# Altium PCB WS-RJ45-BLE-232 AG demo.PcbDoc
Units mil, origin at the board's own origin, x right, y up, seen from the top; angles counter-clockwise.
Board outline 2362.2 x 1181.1 mil, 3 copper layers (Top Layer, Mid-Layer 1, Bottom Layer), stack 74.411 mil thick; 17 components, 28 nets, 68 pads, 0 vias.
Unrouted connection lines stored in the file: 9.
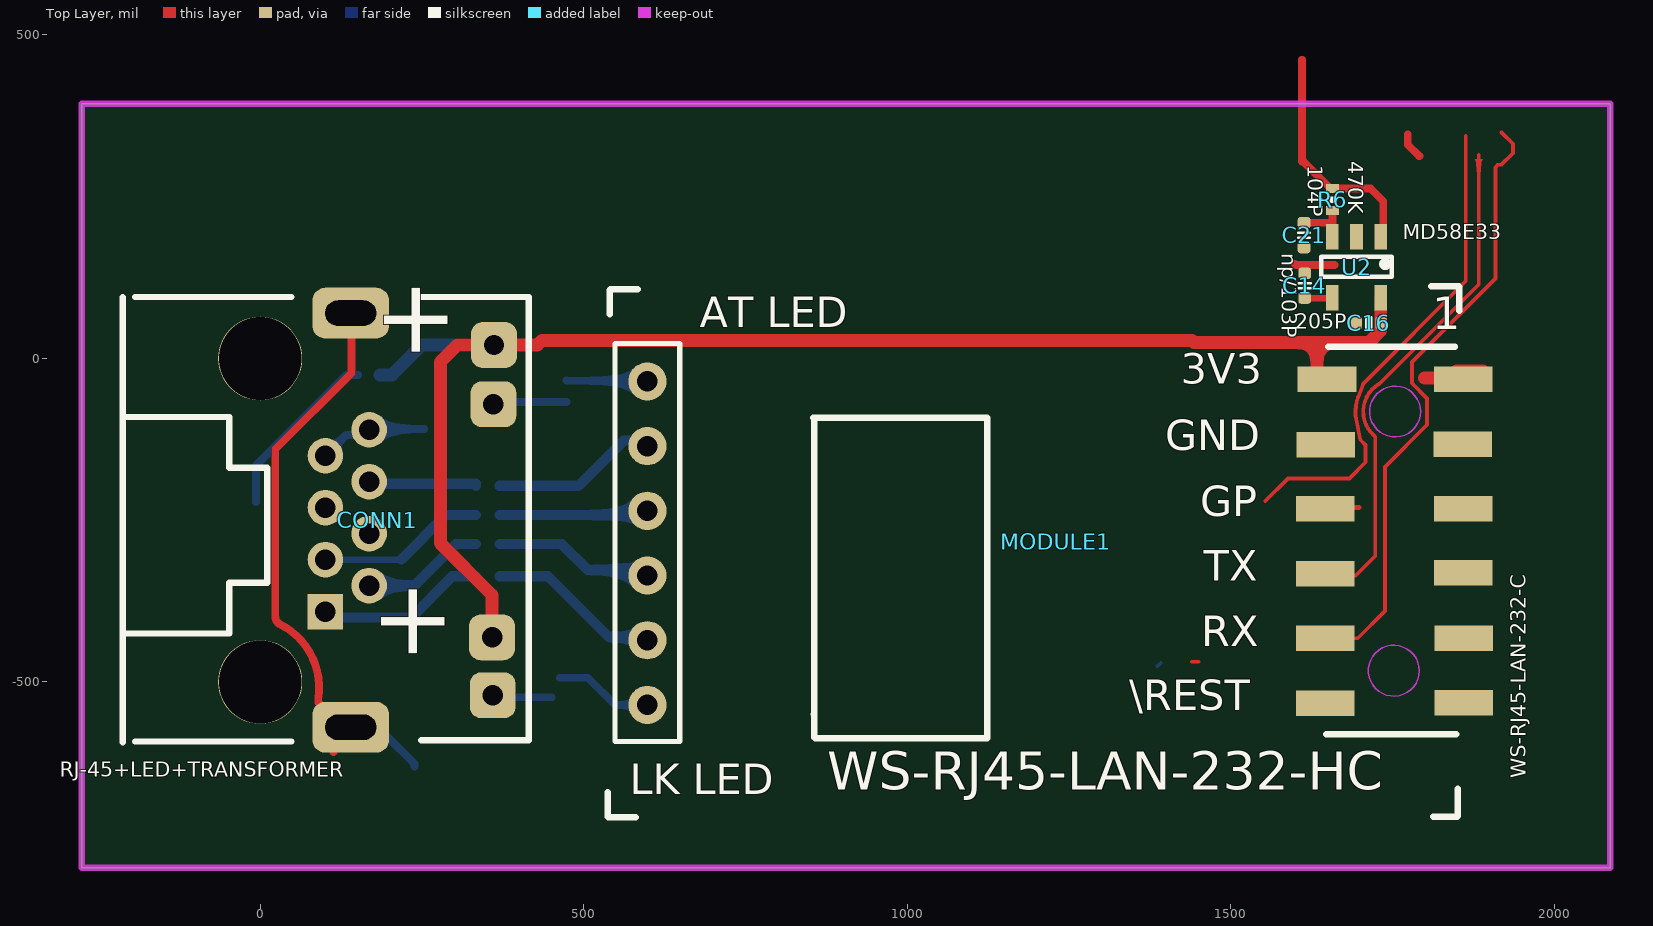
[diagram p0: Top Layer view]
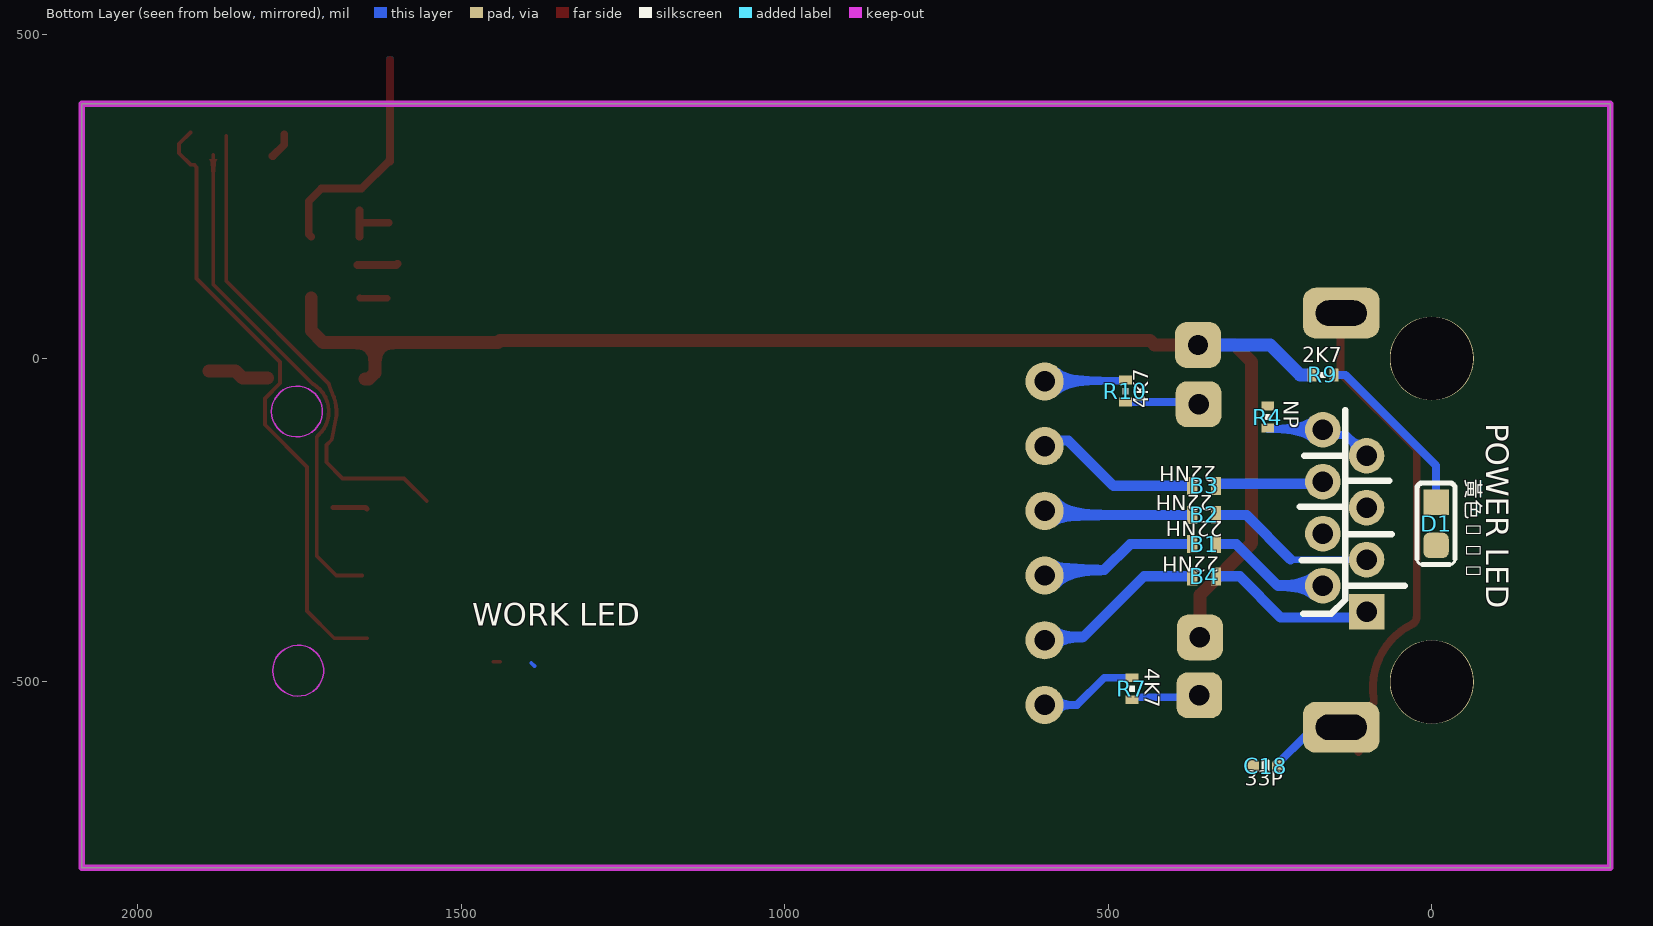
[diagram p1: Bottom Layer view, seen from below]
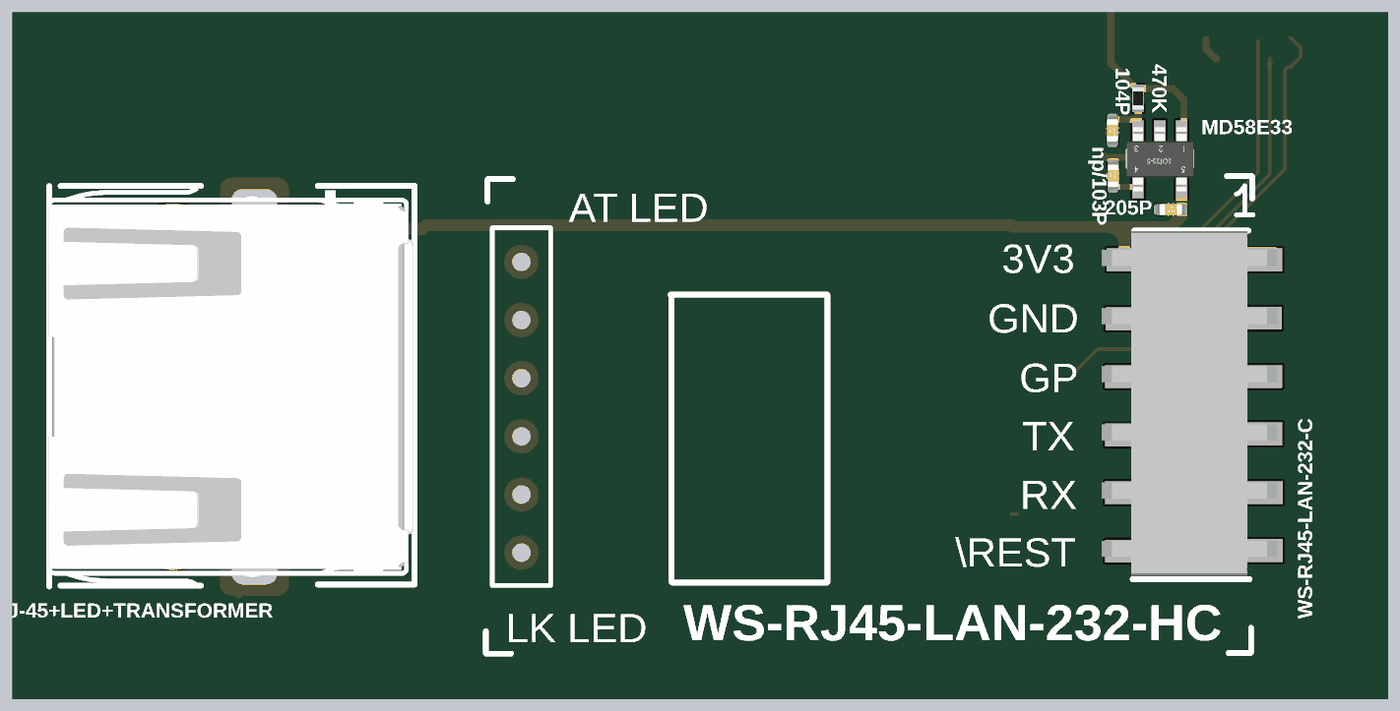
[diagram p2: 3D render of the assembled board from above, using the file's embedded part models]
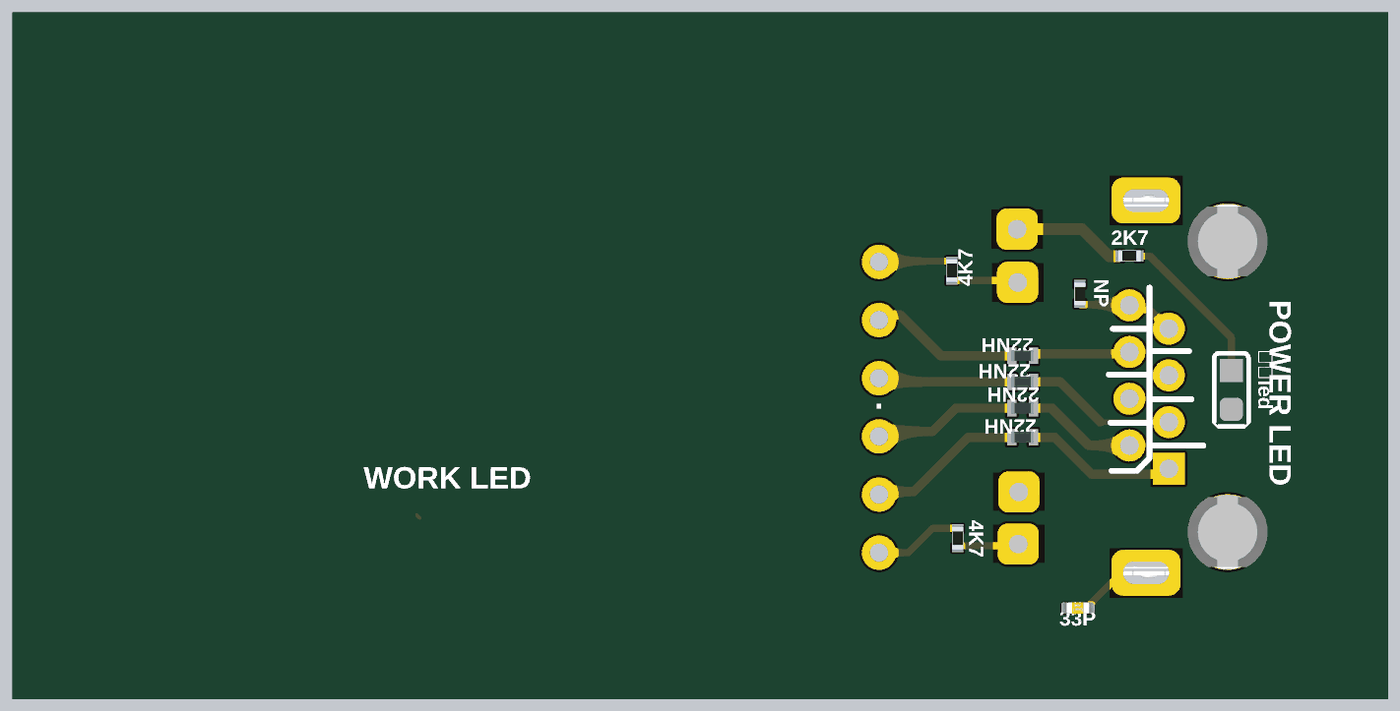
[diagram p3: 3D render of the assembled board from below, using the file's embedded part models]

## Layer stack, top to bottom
Top Solder: solder mask 1, SM-001, Dk 4
Top Layer: signal copper 1.378
Dielectric 1: core 39.3701, Core-043, Dk 4.3
Mid-Layer 1: signal copper 19.685
Dielectric2: dielectric 12.6, FR-4, Dk 4.8
Bottom Layer: signal copper 1.378
Bottom Solder: solder mask 1, SM-001, Dk 4

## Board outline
-275.59,-787.4 2086.61,-787.4 2086.61,393.7 -275.59,393.7

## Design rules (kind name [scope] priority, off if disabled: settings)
Clearance [All] p1: gap=12 ignorepadtopadclearanceinfootprint=FALSE
PlaneConnect [All] p1: pad.planeconnectstyle=Relief pad.reliefexpansion=20 pad.reliefentries=4 pad.reliefconductorwidth=10 pad.reliefairgap=10 via.planeconnectstyle=Direct via.reliefexpansion=20 via.reliefentries=4 via.reliefconductorwidth=10 via.reliefairgap=10
PolygonConnect [All] p1: thpad.connectstyle=Relief thpad.reliefconductorwidth=10 thpad.reliefentries=4 thpad.polygonreliefangle="90 Angle" thpad.airgapwidth=10 smdpad.connectstyle=Relief smdpad.reliefconductorwidth=16 smdpad.reliefentries=4 smdpad.polygonreliefangle="90 Angle" smdpad.airgapwidth=10 via.connectstyle=Direct via.reliefconductorwidth=10 via.reliefentries=4 via.polygonreliefangle="90 Angle" via.airgapwidth=10
RoomDefinition "WS-RJ45-BLE-232 AG demo" [InComponentClass('WS-RJ45-BLE-232 AG demo')] p1: confinementstyle=ConfineIn formatcopy=TRUE lockcomponents=FALSE outline -4486.12,-4550.58 -2486.12,-4550.58 -2486.12,-3550.58 -4486.12,-3550.58
RoutingVias [All] p1: holewidth=28 width=50 viastyle="Through Hole" minholewidth=28 minwidth=50 maxholewidth=28 maxwidth=50
SolderMaskExpansion [All] p1: expansion=4 istentingtop=FALSE
SupplyNets "Schematic Supply Nets_1" [InNet('GND')] p1: voltage=0.000
SupplyNets "Schematic Supply Nets" [InNet('4.5V')] p2: voltage=0.000
Width [All] p1: maxlimit=100 minlimit=6 preferedwidth=10
29 further rules are at their usual default settings.

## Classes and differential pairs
component class "WS-RJ45-BLE-232 AG demo": B1 B2 B3 B4 C14 C16 C18 CONN1 D1 MODULE1 R4 R6 R7 R9 R10 U2

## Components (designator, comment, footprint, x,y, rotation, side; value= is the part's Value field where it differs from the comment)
B1 "22NH" B0402 352.09,-286.87 r0 bottom
B2 "22NH" B0402 352.09,-241.87 r0 bottom
B3 "22NH" B0402 352.09,-196.87 r0 bottom
B4 "22NH" B0402 352.09,-336.87 r0 bottom locked
C14 "np/103P" CAP0402 1614.5,112.53 r90 top
C16 "205P" CAP0402 1713.5,54.53 r0 top
C18 "33P" CAP0402 257,-630.47 r180 bottom
C21 "104P" CAP0402 1613.5,190.53 r90 top
CONN1 "RJ-45+LED+TRANSFORMER" RJ45-led 168.5,-110.16 r90 top locked
D1 "黃色led" "LED 0603_GREEN" -6.5,-255.47 r90 bottom
MODULE1 "WS-RJ45-LAN-232-C" "WS-RJ45-LAN-232-C -HC" 364.55,-31.83 r0 top locked
R4 "NP" R0402 253.5,-90.47 r90 bottom
R6 "470K" R0402 1657.5,245.53 r90 top
R7 "4K7" R0402 463.5,-510.47 r270 bottom
R9 "2K7" R0402 168.5,-25.47 r180 bottom
R10 "4K7" R0402 473.5,-50.47 r90 bottom
U2 "MD58E33" SOT23-5 1732.09,188.13 r180 top

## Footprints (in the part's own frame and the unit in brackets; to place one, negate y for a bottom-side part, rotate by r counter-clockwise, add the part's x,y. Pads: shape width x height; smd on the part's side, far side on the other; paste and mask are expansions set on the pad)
B0402 [mil] "BEAD0402磁珠"
  rect 16x28 smd: 1(-18.5,0) 2(18.5,0)
  body extent -20,-10 20,10, height 20
CAP0402 [mm]
  rrect50% 0.45x0.5 smd mask+0.05: 1(-0.485,0) 2(0.485,0)
  silkscreen extent -0.1,-0.23 0.1,0.23, body extent -0.73,-0.25 0.73,0.25, height 0.51
"LED 0603_GREEN" [mm]
  rect 1x1 smd paste+0 mask+0: 1(0.85,0)
  rrect50% 1x1 smd paste+0 mask+0: 2(-0.85,0)
  silkscreen extent -1.6,-0.75 1.6,0.75, body extent -0.92,-0.53 1.09,0.53, height 0.46
R0402 [mm] "0402電阻"
  rect 0.35x0.5 smd mask+0.08: 1(-0.432,0) 2(0.432,0)
  silkscreen extent -0.13,-0.13 0.12,0.12, body extent -0.6,-0.25 0.6,0.25, height 0.35
RJ45-led [mm]
  rrect50% 2x3 hole 2 slot 1 at 0 deg mask+0.102: 0(-11.68,0.724) 0(4.576,0.724)
  rect 1.397x1.397 hole 0.8 mask+0.102: 1(-7.14,1.718)
  round 1.397 hole 0.8 mask+0.102: 2(-6.12,0) 3(-5.1,1.718) 4(-4.08,0) 5(-3.06,1.718) 6(-2.04,0) 7(-1.02,1.718) 8(0,0)
  rrect50% 1.8x1.8 hole 0.8 mask+0.102: 9(-10.425,-4.85) 10(-8.15,-4.825) 11(1,-4.875) 12(3.325,-4.9)
  round 3.302 hole 3.25 unplated: 13(-9.902,4.28) 14(2.798,4.28)
  silkscreen extent -12.27,-6.26 5.21,9.68, body extent -12.31,-6.21 5.2,9.74, height 3.23
SOT23-5 [mm]
  rect 0.5x1 smd: 1(0,0) 2(0.95,0) 3(1.9,0) 4(1.9,2.4) 5(0,2.4)
  silkscreen extent -0.43,0.79 2.34,1.57, body extent -0.5,-0.2 2.4,2.6, height 1.09
"WS-RJ45-LAN-232-C -HC" [mm]
  round 1.5 hole 0.8 mask+0.102: 1(5.942,-0.092) 2(5.942,-2.632) 3(5.942,-5.172) 4(5.942,-7.712) 5(5.942,-10.252) 6(5.942,-12.792)
  rect 0.2x0.2 on Bottom Overlay: 2(5.942,-6.392)
  rect 2.3x1 smd mask+0.102: B1(37.975,0) B2(32.625,0) B3(37.95,-2.55) B4(32.575,-2.575) B5(37.975,-5.1) B6(32.55,-5.1) B7(37.975,-7.6) B8(32.55,-7.65) B9(38,-10.175) B10(32.55,-10.175) B11(38,-12.7) B12(32.55,-12.725)
  Keep-Out Layer circle w0.051: c35.25,-11.45 r1
  Keep-Out Layer circle w0.051: c35.3,-1.275 r1
  silkscreen extent 4.39,-17.2 37.81,3.65, body extent 4.32,-17.23 40.06,3.52, height 9.59

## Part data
B1 B2 B3 B4: library part BEAD
C14 C16 C18 C21: library part "CAP NP"
CONN1: library part RJ-45
D1: library part LED
MODULE1: "WENSHING ELECTRO MODULE"
R4 R6 R7 R9 R10: library part R
U2: library part MIC5219-3.3BM5

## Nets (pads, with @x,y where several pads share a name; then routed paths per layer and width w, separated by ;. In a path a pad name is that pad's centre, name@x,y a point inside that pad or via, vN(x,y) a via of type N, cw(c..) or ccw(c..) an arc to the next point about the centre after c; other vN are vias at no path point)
4.5V: R6.2 U2.1 | length 364.4
  Top Layer w12: 1610.53,461.56 1610.53,304.53 1612.55,304.53 1654.55,262.53 R6.2 1716.5,262.53 1735.93,243.1 1735.93,191.97 U2.1
GND: C14.2 C16.1 C18.1 C21.1 D1.2 MODULE1.B3 MODULE1.B4 R4.2 U2.2 | length 62.4
  Top Layer w12: 1598.83,146.3 1600.61,144.53 1660.5,144.53
NetB1_1: B1.1 CONN1.2 | length 191.7
  Bottom Layer w16: CONN1.2 237.87,-351.1 302.1,-286.87 B1.1
NetB1_2: B1.2 MODULE1.4 | length 251.5
  Bottom Layer w16: B1.2 466.46,-286.87 506.46,-326.87 MODULE1.4@598.5,-326.87 ; MODULE1.4 MODULE1.4@603.46,-330.51
NetB2_1: B2.1 CONN1.3 | length 261.3
  Bottom Layer w10: CONN1.3 218.03,-310.94 218.5,-310.47
  Bottom Layer w16: 218.5,-310.47 287.1,-241.87 B2.1
NetB2_2: B2.2 MODULE1.3 | length 240.4
  Bottom Layer w16: B2.2 594.9,-241.87 MODULE1.3@606.26,-230.51
NetB3_1: B3.1 CONN1.6 | length 169.6
  Bottom Layer w16: CONN1.6 171.7,-193.67 333.59,-193.67 B3.1
NetB3_2: B3.2 MODULE1.2@598.5,-135.47 | length 260.3
  Bottom Layer w16: B3.2 492.1,-196.87 562.1,-126.87 594.9,-126.87 598.54,-130.51 MODULE1.2@596.72,-130.51
NetB4_1: B4.1 CONN1.1 | length 251.4
  Bottom Layer w16: CONN1.1@108.5,-400.47 233.5,-400.47 297.1,-336.87 B4.1
NetB4_2: B4.2 MODULE1.5 | length 266.7
  Bottom Layer w16: B4.2 444.9,-336.87 538.54,-430.51 MODULE1.5@598.5,-430.51
NetC14_1: C14.1 U2.4 | length 42.9
  Top Layer w10: C14.1 1657.07,93.43 U2.4
NetC16_2: C16.2 CONN1.10 CONN1.12 MODULE1.B1 MODULE1.B2 R9.1 U2.5 | length 2341.5
  Top Layer w20: CONN1.10 358.46,-365.43 278.5,-285.47 278.5,-5.47 304.72,20.75 428.56,20.75 435.33,27.53 1440.5,27.53 1443.5,24.53 1633.5,24.53 ; MODULE1.B2 1643.19,-31.83 1633.5,-22.15 1633.5,24.53 ; U2.5 1732.09,53.13 1732.09,43.11 1713.5,24.53 1633.5,24.53 ; 1799.45,-30.47 1837.93,-30.47 1848.88,-19.52 MODULE1.B1@1889.76,-19.52
  Bottom Layer w20: R9.1 203.5,-25.47 249.72,20.75 CONN1.12
NetC18_2: C18.2 CONN1.0 | length 897.7
  Top Layer w12: CONN1.0@113.5,-608.21 113.5,-581.84 113.5,-555.47 89.79,-531.76 89.79,-526.79 89.79,-525.86 ccw(c-18.08,-508.62) 30.15,-410.61 cw(c35.5,-399.87) 23.58,-401.28 23.5,-400.58 23.5,-399.87 23.5,-140.47 141.22,-22.76 CONN1.0@141.22,54.53
  Bottom Layer w12: CONN1.0@111.22,-580.93 192.89,-580.93 238.5,-626.54 C18.2@238.5,-630.47
NetC21_2: C21.2 R6.1 U2.3 | length 85.8
  Top Layer w12: C21.2@1612.52,209.62 C21.2 1656.59,209.62 1657.39,210.42 ; U2.3 1657.39,188.24 1657.39,210.42 ; 1657.5,210.53 1657.39,210.42 ; R6.1 1657.39,228.42 1657.39,210.42
NetCONN1_7: CONN1.7 CONN1.8 R4.1 | length 169.3
  Bottom Layer w12: CONN1.7 133.04,-118.14 160.52,-118.14 CONN1.8 ; CONN1.8@168.5,-108.97 R4.1@253.5,-108.97
NetCONN1_9: CONN1.9 R7.2 | length 96
  Bottom Layer w12: CONN1.9@355.66,-526.52 358.62,-523.55 450.42,-523.55
NetCONN1_11: CONN1.11 R10.1 | length 104.8
  Bottom Layer w12: CONN1.11@368.74,-67.47 R10.1
NetD1_1: D1.1 R9.2 | length 272.5
  Bottom Layer w12: D1.1 -6.5,-165.47 133.5,-25.47 R9.2
NetMODULE1_1: MODULE1.1 R10.2 | length 125.8
  Bottom Layer w12: R10.2 474.39,-34.36 597.39,-34.36 MODULE1.1
NetMODULE1_6: MODULE1.6 R7.1 | length 152.4
  Bottom Layer w12: R7.1 506.5,-493.47 548.5,-535.47 MODULE1.6
NetMODULE1_B5: MODULE1.B5
NetMODULE1_B6: MODULE1.B6 | length 53.3
  Top Layer w8: MODULE1.B6 1648.19,-230.47 1698.5,-230.47
NetMODULE1_B7: MODULE1.B7
NetMODULE1_B8: MODULE1.B8 | length 780.7
  Top Layer w6: MODULE1.B8@1653.5,-335.47 1693.5,-335.47 1723.5,-305.47 1723.5,-120.9 1721.74,-119.15 1721.61,-119.02 cw(c1754.31,-82.03) 1729.8,-39.17 1883.5,114.53 1883.5,314.53
NetMODULE1_B9: MODULE1.B9
NetMODULE1_B10: MODULE1.B10 | length 961.4
  Top Layer w6: MODULE1.B10 1696.55,-432.42 1738.5,-390.47 1738.5,-167.66 1803.68,-102.48 1803.68,-61.58 1780.45,-38.34 1780.45,-5.5 1909.48,123.54 1909.48,295.51 1913.5,299.53 1918.76,299.53 1936.36,317.13 1936.36,331.92 1918.76,349.53
NetMODULE1_B11: MODULE1.B11
NetMODULE1_B12: MODULE1.B12
pads on no net: CONN1.4 CONN1.5 CONN1.13 CONN1.14 MODULE1.2@598.5,-283.5
copper on no net: | length 814.7
  Top Layer w6: 1440.13,-468.84 1450.13,-468.84 ; 1553.5,-220.47 1588.5,-185.47 1683.5,-185.47 1708.5,-160.47 1708.5,-133.71 1700.44,-125.65 1694.13,-94.04 cw(c1754.31,-82.03) 1697.1,-59.83 1704.85,-39.84 1705.31,-38.66 1706.2,-37.77 1863.5,119.53 1863.5,344.1
  Top Layer w12: 1773.91,346.63 1773.91,330.32 1791.1,313.13 1792.09,313.13
  Bottom Layer w6: 1386.97,-475.47 1391.97,-470.47

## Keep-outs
Keep-Out Layer:
  lines w10: -275.59,-787.4 -236.22,-787.4 2086.61,-787.4 2086.61,393.7 -275.59,393.7 -275.59,-787.4

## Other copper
Top Layer:
  pour cut-out: 617,68.53 617,-641.47 -238,-641.47 -238,68.53

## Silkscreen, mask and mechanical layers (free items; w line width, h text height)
Bottom Overlay:
  text "POWER LED" at -72.21,-100.47 h60 r90
  text "WORK LED" at 1483.5,-424.77 h60

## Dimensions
-2651.5,-970.47 to 4198.5,-980.47 on Mechanical 1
